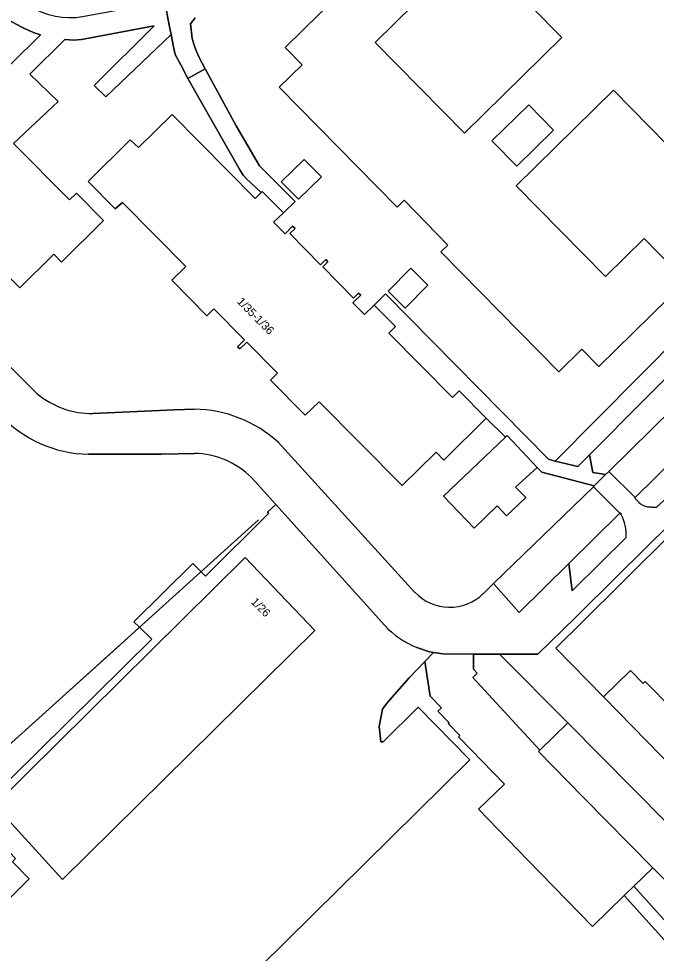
# Model space of a CAD drawing. Extents: x 162788 to 163838, y 385791 to 386523.
# Drawn here: x 162931.3 to 163008.9, y 385931.9 to 386045.6 of the extents above; entities that cross this region are included whole.
import ezdxf

# ---------------------------------------------------------------- set-up
doc = ezdxf.new("R2010")
doc.units = 0
for name, color, linetype in [('IMGEO_Berm_groen', 7, 'Continuous'), ('IMGEO_Erf', 7, 'Continuous'), ('IMGEO_Grasland_overig', 7, 'Continuous'), ('IMGEO_Groenvoorziening', 7, 'Continuous'), ('IMGEO_Hek', 7, 'Continuous'), ('IMGEO_Loofbos', 7, 'Continuous'), ('IMGEO_Pand', 7, 'Continuous'), ('IMGEO_Pand_nummerreeks', 7, 'Continuous'), ('IMGEO_Parkeervlak_open', 7, 'Continuous'), ('IMGEO_Rijbaan_lokaal_open', 7, 'Continuous'), ('IMGEO_Terreindeel_open', 7, 'Continuous'), ('IMGEO_Voetpad_halfverhard', 7, 'Continuous'), ('IMGEO_Voetpad_open', 7, 'Continuous'), ('IMGEO_Woonerf_gesloten', 7, 'Continuous'), ('IMGEO_Woonerf_open', 7, 'Continuous')]:
    doc.layers.add(name, color=color, linetype=linetype)

msp = doc.modelspace()

# ---------------------------------------------------------------- linework, layer by layer
at = {"layer": 'IMGEO_Berm_groen'}
msp.add_lwpolyline([(163037.1, 386024.08), (163037.57, 386024.55), (163037.56, 386024.56), (163035.84, 386026.06), (163035.71, 386026.12), (163035.57, 386026.18), (163035.43, 386026.22), (163035.29, 386026.25), (163035.14, 386026.27), (163034.99, 386026.27), (163034.84, 386026.26), (163034.7, 386026.24), (163034.55, 386026.21), (163034.41, 386026.16), (163034.28, 386026.1), (163034.15, 386026.03), (163034.02, 386025.95), (163033.9, 386025.86), (163000.76, 385992.51), (163001.16, 385990.39), (163002.72, 385990.11), (163003.11, 385990.49), (163013.51, 386000.75)], close=True, dxfattribs=at)
for points in [[(163007.83, 385986.19), (163008.88, 385986.1), (163010.28, 385987.4), (163010.56, 385987.68), (163014.14, 385991.17), (163022.06, 385999.15)], [(163011.21, 385992.17), (163006.31, 385987.31), (163006.26, 385987.26), (163006.74, 385986.76)], [(163004.45, 385985.42), (162998.23, 385979.29), (162998.66, 385975.96), (163002.19, 385979.46), (163005.23, 385982.48)], [(163004.62, 385985.28), (163004.49, 385985.47), (163004.45, 385985.42)]]:
    msp.add_lwpolyline(points, dxfattribs=at)
for centre, radius, start, end in [((163008.1, 385988.07), 1.9, 223.8361, 261.8307), ((162999.41, 385982.67), 5.82, 358.0925, 26.6052)]:
    msp.add_arc(centre, radius, start, end, dxfattribs=at)
at = {"layer": 'IMGEO_Erf'}
for points in [[(162979.39, 386047.32), (162974.69, 386042.7), (162985.55, 386031.65), (162997.38, 386043.28), (162986.52, 386054.33)], [(163014.52, 386025.84), (163003.66, 386036.89), (162991.83, 386025.26), (163002.69, 386014.21), (163007.39, 386018.84), (163012.48, 386013.66), (163001.89, 386003.26), (162999.83, 386005.36), (162997.02, 386002.61), (162982.68, 386017.21), (162983.54, 386018.05), (162978.2, 386023.49), (162977.34, 386022.64), (162962.99, 386037.24), (162965.79, 386039.99), (162963.73, 386042.09), (162974.31, 386052.49)], [(162952.77, 386045.68), (162952.2, 386044.97), (162952.43, 386043.16), (162952.65, 386042.36), (162952.93, 386041.59), (162953.26, 386040.86), (162954, 386039.5), (162957.79, 386032.55), (162960.59, 386027.67), (162964.93, 386023.35), (162963.51, 386021.95), (162962.33, 386020.81), (162963.72, 386019.41), (162964.64, 386020.35), (162964.93, 386020.07), (162964.28, 386019.45), (162968.03, 386015.65), (162968.67, 386016.29), (162968.93, 386016.02), (162968.3, 386015.38), (162972.04, 386011.6), (162972.67, 386012.2), (162972.94, 386011.95), (162971.98, 386011.02), (162973.37, 386009.58), (162974.57, 386010.75), (162975.95, 386012.1), (162995.75, 385991.99), (162996.59, 385991.77), (163032.29, 386027.77)], [(162888.58, 386044.93), (162933.53, 386000)], [(162943.93, 386023.24), (162943.07, 386022.44), (162939.78, 386025.76), (162944.89, 386030.83), (162945.89, 386029.9), (162950, 386033.92), (162960.08, 386023.71), (162960.81, 386024.44), (162959.02, 386026.09), (162958.63, 386026.54), (162958.2, 386027.18), (162951.88, 386038.31), (162951.07, 386039.89), (162950.36, 386041.23), (162950.14, 386042.15), (162949.85, 386043.68), (162941.91, 386036.08), (162940.49, 386037.46), (162947.78, 386044.73), (162939.86, 386043.21), (162938.95, 386043.05), (162938.01, 386042.99), (162936.92, 386043.05), (162932.69, 386038.83), (162936.11, 386035.52), (162930.69, 386030.4), (162937.49, 386023.54), (162938.35, 386024.34), (162941.64, 386021.02), (162936.53, 386015.97), (162935.58, 386016.95), (162931.46, 386012.86), (162921.35, 386023.04)], [(162987.84, 385975.64), (162989.09, 385976.86), (163001.24, 385988.64), (163001.34, 385988.73), (162994.95, 385990.42), (162994.39, 385991), (162991.77, 385988.59), (162992.99, 385987.33), (162990.67, 385985.11), (162989.54, 385986.3), (162986.71, 385983.61), (162983, 385987.51), (162990.54, 385994.69), (162988.2, 385996.97), (162983.04, 385991.89), (162982.1, 385992.86), (162977.98, 385988.79), (162967.88, 385998.99), (162966.18, 385997.34), (162961.94, 386001.62), (162962.78, 386002.45), (162959.06, 386006.25), (162958.21, 386005.4), (162957.93, 386005.68), (162958.77, 386006.52), (162955.05, 386010.29), (162954.2, 386009.45), (162949.95, 386013.76), (162951.66, 386015.45), (162943.93, 386023.24)], [(162940.34, 385997.54), (162950.21, 385998), (162952.69, 385998.07)], [(162962.87, 385994.06), (162979.52, 385975.79)], [(162975.87, 385971.76), (162962.58, 385986.48), (162961.58, 385985.54), (162961.71, 385985.4), (162954.04, 385977.77), (162952.52, 385979.29), (162945.32, 385972.22), (162946.01, 385971.54), (162947.5, 385970.08), (162926.89, 385949.75), (162928.94, 385947.68), (162928.43, 385947.18), (162927.86, 385946.61), (162930.93, 385943.42), (162930.55, 385943.02), (162932.57, 385940.93), (162894.88, 385903.13), (162917.15, 385880.93), (162957.72, 385920.28), (162954.26, 385923.85), (162986.21, 385955.41)], [(162986.21, 385955.41), (162979.9, 385961.8), (162975.64, 385957.59), (162975.37, 385957.61), (162975.15, 385959.46), (162975.57, 385961.56), (162976.13, 385962.36), (162978.82, 385965.4), (162980.71, 385967.36), (162981.77, 385968.48), (162981.3, 385968.56), (162979.74, 385969.09)], [(163010.89, 385961.52), (163007.53, 385964.93), (163007.3, 385964.7), (163007.21, 385964.8), (163005.73, 385966.3), (163002.45, 385963.07), (163021.68, 385943.41)], [(163014.44, 385936.23), (163008.47, 385942.28), (163006.16, 385940.04), (163015.06, 385930.12)]]:
    msp.add_lwpolyline(points, dxfattribs=at)
for points in [[(162996.39, 386032.04), (162993.37, 386035.12), (162988.88, 386030.71), (162991.9, 386027.64)], [(162963.26, 386025.74), (162966.03, 386028.47), (162968.14, 386026.34), (162965.37, 386023.61)], [(162976.25, 386012.45), (162979, 386015.22), (162981.09, 386013.15), (162978.35, 386010.38)], [(162936.63, 385940.85), (162928.36, 385949.9), (162958.88, 385980.01), (162967.35, 385971.15), (162964.37, 385968.21)]]:
    msp.add_lwpolyline(points, close=True, dxfattribs=at)
for centre, radius, start, end in [((162940.25, 386007.94), 10.4, 229.7452, 270.482), ((162952.51, 385982.69), 15.38, 47.6678, 89.3535), ((162983.75, 385979.82), 5.84, 223.5423, 314.3637), ((162983.83, 385979.16), 10.88, 222.9008, 247.8814)]:
    msp.add_arc(centre, radius, start, end, dxfattribs=at)
at = {"layer": 'IMGEO_Grasland_overig'}
for points in [[(162894.88, 385903.13), (162932.57, 385940.93), (162930.55, 385943.02), (162930.93, 385943.42), (162927.86, 385946.61), (162928.43, 385947.18), (162928.94, 385947.68), (162926.89, 385949.75), (162947.5, 385970.08), (162946.01, 385971.54), (162943.62, 385969.38), (162933.35, 385960.12), (162894.46, 385925.05)], [(163014.02, 385928.88), (163004.99, 385938.91), (163001.1, 385935.13), (162993.27, 385943.2), (162987.27, 385949.39), (162990.42, 385952.45), (162984.93, 385958.1), (162984.82, 385958.21), (162984.99, 385958.38), (162983.58, 385959.83), (162983.68, 385959.93), (162982.32, 385961.34), (162982.74, 385961.74), (162981.36, 385963.16), (162980.71, 385967.36), (162978.82, 385965.4), (162976.13, 385962.36), (162975.57, 385961.56), (162975.15, 385959.46), (162975.37, 385957.61), (162975.64, 385957.59), (162979.9, 385961.8), (162986.21, 385955.41), (162954.26, 385923.85)]]:
    msp.add_lwpolyline(points, dxfattribs=at)
at = {"layer": 'IMGEO_Groenvoorziening'}
for points in [[(162922, 386047.82), (162922.32, 386047.08), (162925.62, 386043.77), (162929.86, 386039.51), (162930.43, 386040.12), (162933.97, 386043.63), (162933.59, 386043.74), (162933.3, 386043.83), (162933.02, 386043.94), (162932.74, 386044.05), (162932.1, 386044.35), (162931.63, 386044.59), (162929.94, 386045.49), (162926.41, 386047.23), (162923.07, 386048.93), (162922.67, 386048.81), (162922.21, 386048.3)], [(162989.82, 385968.26), (162986.64, 385968.27), (162986.63, 385966.43), (162987.09, 385965.94), (162986.55, 385965.43), (162994.73, 385956.59), (162998.1, 385959.9)]]:
    msp.add_lwpolyline(points, close=True, dxfattribs=at)
at = {"layer": 'IMGEO_Hek'}
msp.add_lwpolyline([(162960.5, 385984.6), (162933.35, 385960.12), (162858.79, 385892.9), (162856.26, 385890.62), (162855.6, 385890.02)], dxfattribs=at)
at = {"layer": 'IMGEO_Loofbos'}
for points in [[(162952.69, 385992.7), (162948.68, 385992.61), (162939.8, 385992.6)], [(162799.91, 385939.85), (162800.2, 385940.21), (162855.27, 385891.58), (162854.65, 385890.88), (162855.13, 385890.45), (162855.6, 385890.02), (162855.6, 385890.02), (162856.26, 385890.62), (162856.67, 385890.99), (162858.79, 385892.9), (162872.11, 385904.91), (162874.36, 385906.94), (162894.46, 385925.05), (162933.35, 385960.12), (162943.62, 385969.38), (162946.01, 385971.54), (162945.32, 385972.22), (162952.52, 385979.29), (162954.04, 385977.77), (162961.71, 385985.4), (162961.58, 385985.54), (162962.58, 385986.48), (162959.63, 385989.75)]]:
    msp.add_lwpolyline(points, dxfattribs=at)
for centre, radius, start, end in [((162940.09, 386007.67), 15.08, 222.9134, 268.8929), ((162952.49, 385982.59), 10.11, 45.1056, 88.8826)]:
    msp.add_arc(centre, radius, start, end, dxfattribs=at)
at = {"layer": 'IMGEO_Pand'}
for points in [[(162986.52, 386054.33), (162997.38, 386043.28), (162985.55, 386031.65), (162974.69, 386042.7), (162979.39, 386047.32)], [(162974.31, 386052.49), (162963.73, 386042.09), (162965.79, 386039.99), (162962.99, 386037.24), (162977.34, 386022.64), (162978.2, 386023.49), (162983.54, 386018.05), (162982.68, 386017.21), (162997.02, 386002.61), (162999.83, 386005.36), (163001.89, 386003.26), (163012.48, 386013.66), (163007.39, 386018.84), (163002.69, 386014.21), (162991.83, 386025.26), (163003.66, 386036.89), (163014.52, 386025.84)], [(162921.35, 386023.04), (162931.46, 386012.86), (162935.58, 386016.95), (162936.53, 386015.97), (162941.64, 386021.02), (162938.35, 386024.34), (162937.49, 386023.54), (162930.69, 386030.4)], [(163010.98, 385983.18), (163004.84, 385977.1), (162999.89, 385972.2), (162996.67, 385968.98), (163002.45, 385963.07), (163005.73, 385966.3), (163007.21, 385964.8), (163007.3, 385964.7), (163007.53, 385964.93), (163010.89, 385961.52)]]:
    msp.add_lwpolyline(points, dxfattribs=at)
for points in [[(162991.9, 386027.64), (162988.88, 386030.71), (162993.37, 386035.12), (162996.39, 386032.04)], [(162968.3, 386015.38), (162968.93, 386016.02), (162968.67, 386016.29), (162968.03, 386015.65), (162964.28, 386019.45), (162964.93, 386020.07), (162964.64, 386020.35), (162963.72, 386019.41), (162962.33, 386020.81), (162963.51, 386021.95), (162960.93, 386024.56), (162960.81, 386024.44), (162960.08, 386023.71), (162950, 386033.92), (162945.89, 386029.9), (162944.89, 386030.83), (162939.78, 386025.76), (162943.07, 386022.44), (162943.93, 386023.24), (162951.66, 386015.45), (162949.95, 386013.76), (162954.2, 386009.45), (162955.05, 386010.29), (162958.77, 386006.52), (162957.93, 386005.68), (162958.21, 386005.4), (162959.06, 386006.25), (162962.78, 386002.45), (162961.94, 386001.62), (162966.18, 385997.34), (162967.88, 385998.99), (162977.98, 385988.79), (162982.1, 385992.86), (162983.04, 385991.89), (162988.2, 385996.97), (162984.9, 386000.3), (162984.08, 385999.49), (162976.34, 386007.34), (162977.15, 386008.15), (162974.57, 386010.75), (162973.37, 386009.58), (162971.98, 386011.02), (162972.94, 386011.95), (162972.67, 386012.2), (162972.04, 386011.6)], [(162963.26, 386025.74), (162965.37, 386023.61), (162968.14, 386026.34), (162966.03, 386028.47)], [(162976.25, 386012.45), (162978.35, 386010.38), (162981.09, 386013.15), (162979, 386015.22)], [(162991.77, 385988.59), (162994.39, 385991), (162990.72, 385994.86), (162990.54, 385994.69), (162983, 385987.51), (162986.71, 385983.61), (162989.54, 385986.3), (162990.67, 385985.11), (162992.99, 385987.33)], [(162967.35, 385971.15), (162958.88, 385980.01), (162928.36, 385949.9), (162936.63, 385940.85), (162964.37, 385968.21)]]:
    msp.add_lwpolyline(points, close=True, dxfattribs=at)
at = {"layer": 'IMGEO_Parkeervlak_open'}
msp.add_lwpolyline([(162998.1, 385959.9), (162994.73, 385956.59), (162994.55, 385956.41), (163000, 385950.88), (163008.47, 385942.28), (163014.44, 385936.23), (163018.03, 385939.78)], close=True, dxfattribs=at)
at = {"layer": 'IMGEO_Rijbaan_lokaal_open'}
msp.add_lwpolyline([(163002.45, 385963.07), (162996.67, 385968.98), (162999.89, 385972.2), (163004.84, 385977.1), (163010.98, 385983.18), (163011.38, 385983.48), (163022.72, 385972), (163022.35, 385971.68), (163023.14, 385970.88), (163025.12, 385972.86), (163024.42, 385973.58), (163025.76, 385974.9), (163018.7, 385982.02), (163017.47, 385980.63), (163012.36, 385985.85), (163010.64, 385984.19), (163004.18, 385977.79), (162999.07, 385972.74), (162994.48, 385968.27), (162989.82, 385968.26), (162998.1, 385959.9), (163018.03, 385939.78), (163021.68, 385943.41)], close=True, dxfattribs=at)
at = {"layer": 'IMGEO_Terreindeel_open'}
msp.add_lwpolyline([(163000, 385950.88), (162994.55, 385956.41), (162994.73, 385956.59), (162986.55, 385965.43), (162987.09, 385965.94), (162986.63, 385966.43), (162986.64, 385968.27), (162982.93, 385968.29), (162981.77, 385968.48), (162980.71, 385967.36), (162981.36, 385963.16), (162982.74, 385961.74), (162982.32, 385961.34), (162983.68, 385959.93), (162983.58, 385959.83), (162984.99, 385958.38), (162984.82, 385958.21), (162984.93, 385958.1), (162990.42, 385952.45), (162987.27, 385949.39), (162993.27, 385943.2), (163001.1, 385935.13), (163004.99, 385938.91), (163006.16, 385940.04), (163008.47, 385942.28)], close=True, dxfattribs=at)
at = {"layer": 'IMGEO_Voetpad_halfverhard'}
msp.add_lwpolyline([(163015.06, 385930.12), (163006.16, 385940.04), (163004.99, 385938.91), (163014.02, 385928.88), (163014.75, 385928.07), (163010.51, 385924.23), (163011.77, 385922.31), (163013.34, 385918.64), (163014.61, 385915.64), (163018.11, 385918.08), (163016.59, 385921.55), (163015.1, 385924.93), (163016.55, 385926.06), (163019.49, 385929), (163052.33, 385958.14), (163098.66, 386000)], dxfattribs=at)
at = {"layer": 'IMGEO_Voetpad_open'}
msp.add_lwpolyline([(162975.95, 386012.1), (162974.57, 386010.75), (162977.15, 386008.15), (162976.34, 386007.34), (162984.08, 385999.49), (162984.9, 386000.3), (162988.2, 385996.97), (162990.54, 385994.69), (162990.72, 385994.86), (162994.39, 385991), (162994.95, 385990.42), (163001.34, 385988.73), (163002.72, 385990.11), (163001.16, 385990.39), (163000.76, 385992.51), (162999.35, 385991.1), (162996.59, 385991.77), (162995.75, 385991.99)], close=True, dxfattribs=at)
at = {"layer": 'IMGEO_Woonerf_gesloten'}
for points in [[(162949.1, 386047.65), (162949.63, 386044.8), (162949.85, 386043.68), (162950.14, 386042.15), (162950.36, 386041.23), (162951.07, 386039.89), (162951.88, 386038.31), (162954, 386039.5), (162953.26, 386040.86), (162952.93, 386041.59), (162952.65, 386042.36), (162952.43, 386043.16), (162952.2, 386044.97), (162952.77, 386045.68)], [(162933.53, 386000), (162888.58, 386044.93)], [(163032.29, 386027.77), (162996.59, 385991.77), (162999.35, 385991.1), (163000.76, 385992.51), (163033.9, 386025.86)], [(162952.69, 385998.07), (162950.21, 385998), (162940.34, 385997.54)], [(162979.52, 385975.79), (162962.87, 385994.06)], [(162939.8, 385992.6), (162948.68, 385992.61), (162952.69, 385992.7)], [(163006.74, 385986.76), (163006.26, 385987.26), (163006.31, 385987.31), (163003.11, 385990.49), (163002.72, 385990.11), (163001.34, 385988.73), (163001.24, 385988.64), (163004.45, 385985.42), (163004.49, 385985.47), (163004.62, 385985.28)], [(162959.63, 385989.75), (162962.58, 385986.48), (162975.87, 385971.76)], [(162979.74, 385969.09), (162981.3, 385968.56), (162981.77, 385968.48), (162982.93, 385968.29), (162986.64, 385968.27), (162989.82, 385968.26), (162994.48, 385968.27), (162999.07, 385972.74), (163004.18, 385977.79), (163010.64, 385984.19), (163012.36, 385985.85), (163010.56, 385987.68), (163010.28, 385987.4), (163008.88, 385986.1), (163007.83, 385986.19)], [(163005.23, 385982.48), (163002.19, 385979.46), (162998.66, 385975.96), (162998.23, 385979.29), (162992.2, 385973.35), (162989.09, 385976.86), (162987.84, 385975.64)]]:
    msp.add_lwpolyline(points, dxfattribs=at)
for centre, radius, start, end in [((162940.25, 386007.94), 10.4, 229.7452, 270.482), ((162952.51, 385982.69), 15.38, 47.6678, 89.3535), ((162940.09, 386007.67), 15.08, 222.9134, 268.8929), ((162952.49, 385982.59), 10.11, 45.1056, 88.8826), ((163008.1, 385988.07), 1.9, 223.8361, 261.8307), ((162999.41, 385982.67), 5.82, 358.0925, 26.6052), ((162983.75, 385979.82), 5.84, 223.5423, 314.3637), ((162983.83, 385979.16), 10.88, 222.9008, 247.8814)]:
    msp.add_arc(centre, radius, start, end, dxfattribs=at)
at = {"layer": 'IMGEO_Woonerf_open'}
for points in [[(162930.69, 386030.4), (162936.11, 386035.52), (162932.69, 386038.83), (162936.92, 386043.05), (162938.01, 386042.99), (162938.95, 386043.05), (162939.86, 386043.21), (162947.78, 386044.73), (162940.49, 386037.46), (162941.91, 386036.08), (162949.85, 386043.68), (162949.63, 386044.8), (162949.1, 386047.65), (162939.09, 386045.8), (162938.27, 386045.71), (162937.43, 386045.68), (162936.61, 386045.73), (162935.79, 386045.86), (162934.98, 386046.06), (162934.19, 386046.33), (162933.44, 386046.66), (162928.28, 386049.3)], [(162929.94, 386045.49), (162931.63, 386044.59), (162932.1, 386044.35), (162932.74, 386044.05), (162933.02, 386043.94), (162933.3, 386043.83), (162933.59, 386043.74), (162933.97, 386043.63), (162930.43, 386040.12)], [(163028.35, 386008.16), (163030.48, 386010.27), (163030.81, 386010.6), (163030.86, 386010.65), (163030.91, 386010.7), (163040.96, 386020.64), (163041.15, 386020.84), (163041.21, 386020.9), (163037.57, 386024.55), (163037.1, 386024.08), (163013.51, 386000.75), (163003.11, 385990.49), (163006.31, 385987.31), (163011.21, 385992.17)]]:
    msp.add_lwpolyline(points, dxfattribs=at)
for points in [[(162957.79, 386032.55), (162954, 386039.5), (162951.88, 386038.31), (162958.2, 386027.18), (162958.63, 386026.54), (162959.02, 386026.09), (162960.81, 386024.44), (162960.93, 386024.56), (162963.51, 386021.95), (162964.93, 386023.35), (162960.59, 386027.67)], [(163004.45, 385985.42), (163001.24, 385988.64), (162989.09, 385976.86), (162992.2, 385973.35), (162998.23, 385979.29)]]:
    msp.add_lwpolyline(points, close=True, dxfattribs=at)

# ---------------------------------------------------------------- texts
at = {"layer": 'IMGEO_Pand_nummerreeks'}
for s, rotation, p in [('1/35-1/36', 314.6962, (162957.8, 386011.08)), ('1/26', 314.3544, (162959.5, 385974.56))]:
    msp.add_text(s, height=1, rotation=rotation, dxfattribs=at).set_placement(p)

doc.saveas('drawing.dxf')
